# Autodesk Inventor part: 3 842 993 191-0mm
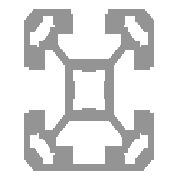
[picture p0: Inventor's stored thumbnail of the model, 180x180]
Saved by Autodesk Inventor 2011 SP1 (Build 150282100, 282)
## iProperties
Category: End -/-
Created: 2011-02
Part Number: 3 842 993 191-0mm
Document SubType Name: Modeling
Designer: SRW
Density: 2.71 g/cm^3
Categories: <MemberInstance><Categories><Category DisplayName="Structural Shapes" InternalName="089c4875-fa83-4c05-b084-43b9cc11f5ed" Mnemonic="GRDR"><CategoryParameter Dis
Stock Number: 3 842 993 191
Description: PROFILE 40x40 3S, -/-
Material: Aluminum-6061
Mass: 39.2557 g
Surface Area: 143.631 cm^2
Volume: 14.4855 cm^3
G_L: 25.000 mm
Author: SRW
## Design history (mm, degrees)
node "Blocks"
  sketch "40X403S"
    geometry: L1 (36.269, 30.157)-(33.329, 30.157); L2 (36.069, 38.957)-(36.069, 43.457); L3 (41.319, 38.957)-(36.069, 38.957); L4 (37.155, 32.457)-(41.319, 36.622); L5 (41.319, 36.622)-(41.319, 38.957); L6 (42.819, 40.457)-(42.819, 39.457); L7 (46.569, 36.707)-(46.569, 34.457); L8 (45.569, 36.707)-(46.569, 36.707); L9 (49.569, 34.457)-(49.569, 39.457); L10 (40.569, 40.457)-(42.819, 40.457); L11 (36.069, 43.457)-(26.069, 43.457); L12 (26.069, 43.457)-(26.069, 38.957); L13 (26.069, 38.957)-(20.819, 38.957); L14 (19.319, 40.457)-(21.569, 40.457); L15 (19.319, 39.457)-(19.319, 40.457); L16 (16.569, 43.457)-(16.569, 42.207); L17 (21.569, 43.457)-(16.569, 43.457); L18 (20.819, 38.957)-(20.819, 36.622); L19 (13.819, 39.457)-(12.569, 39.457); L20 (17.069, 35.007)-(19.605, 35.007); L21 (15.569, 34.457)-(15.569, 36.707); L22 (12.569, 39.457)-(12.569, 34.457); L23 (24.983, 32.457)-(37.155, 32.457); L24 (20.819, 36.622)-(24.983, 32.457); L25 (19.605, 35.007)-(23.569, 31.043); L26 (11.069, 30.757)-(12.569, 30.757); L27 (28.808, 30.157)-(25.869, 30.157); L28 (29.076, 29.543)-(28.808, 30.157); L29 (17.069, 29.957)-(17.069, 35.007); L30 (12.569, 29.957)-(17.069, 29.957); L31 (12.569, 30.757)-(12.569, 29.957); L32 (11.069, 41.957)-(11.069, 30.757); L33 (48.069, 44.957)-(14.069, 44.957); L34 (15.569, 36.707)-(16.569, 36.707); L35 (49.569, 19.157)-(49.569, 19.957); L36 (51.069, 19.157)-(49.569, 19.157); L37 (49.569, 10.457)-(49.569, 15.457); L38 (48.319, 10.457)-(49.569, 10.457); L39 (46.569, 15.457)-(46.569, 13.207); L40 (46.569, 13.207)-(45.569, 13.207); L41 (45.069, 19.957)-(45.069, 14.907); L42 (49.569, 19.957)-(45.069, 19.957); L43 (51.069, 7.957)-(51.069, 19.157); L44 (42.533, 14.907)-(38.569, 18.872); L45 (37.155, 17.457)-(41.119, 13.493); L46 (45.069, 14.907)-(42.533, 14.907); L47 (41.119, 13.493)-(41.119, 10.957); L48 (41.119, 10.957)-(36.069, 10.957); L49 (36.069, 6.457)-(36.869, 6.457); L50 (36.069, 10.957)-(36.069, 6.457); L51 (42.819, 9.457)-(40.569, 9.457); L52 (36.869, 6.457)-(36.869, 4.957); L53 (45.569, 6.457)-(45.569, 7.707); L54 (40.569, 6.457)-(45.569, 6.457); L55 (36.869, 4.957)-(48.069, 4.957); L56 (42.819, 10.457)-(42.819, 9.457); L57 (23.569, 31.043)-(23.569, 18.872); L58 (33.329, 19.757)-(36.269, 19.757); L59 (36.269, 19.757)-(36.269, 22.697); L60 (33.062, 20.372)-(33.329, 19.757); L61 (36.269, 22.697)-(35.654, 22.964); L62 (28.808, 19.757)-(29.076, 20.372); L63 (24.983, 17.457)-(37.155, 17.457); L64 (35.654, 26.951)-(36.269, 27.218)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; A1 r 2.75 centre (45.569, 39.457) between (42.819, 39.457) and (45.569, 36.707); A2 r 1.5 centre (48.069, 34.457) between (46.569, 34.457) and (49.569, 34.457); A3 r 1.5 centre (21.569, 41.957) between (21.569, 40.457) and (21.569, 43.457); A4 r 2.75 centre (16.569, 39.457) between (16.569, 36.707) and (19.319, 39.457); A5 r 2.75 centre (16.569, 39.457) between (16.569, 42.207) and (13.819, 39.457); A6 r 3 centre (14.069, 41.957) between (14.069, 44.957) and (11.069, 41.957); A7 r 1.5 centre (14.069, 34.457) between (12.569, 34.457) and (15.569, 34.457); A8 r 3 centre (48.069, 7.957) between (48.069, 4.957) and (51.069, 7.957); A9 r 1.5 centre (48.069, 15.457) between (49.569, 15.457) and (46.569, 15.457); A10 r 2.75 centre (45.569, 10.457) between (45.569, 7.707) and (48.319, 10.457); A11 r 2.75 centre (45.569, 10.457) between (45.569, 13.207) and (42.819, 10.457); A12 r 1.5 centre (40.569, 7.957) between (40.569, 9.457) and (40.569, 6.457); A13 r 5 centre (31.069, 24.957) between (29.076, 20.372) and (33.062, 20.372); A14 r 5 centre (31.069, 24.957) between (35.654, 22.964) and (35.654, 26.951); A15 r 5 centre (31.069, 24.957) between (33.062, 29.543) and (29.076, 29.543); A16 r 5 centre (31.069, 24.957) between (26.483, 26.951) and (26.483, 22.964); A17 r 3 centre (14.069, 7.957) between (11.069, 7.957) and (14.069, 4.957); A18 r 2.75 centre (16.569, 10.457) between (19.319, 10.457) and (16.569, 13.207); A19 r 1.5 centre (14.069, 15.457) between (15.569, 15.457) and (12.569, 15.457); A20 r 2.75 centre (16.569, 10.457) between (13.819, 10.457) and (16.569, 7.707); A21 r 1.5 centre (21.569, 7.957) between (21.569, 6.457) and (21.569, 9.457); A22 r 3 centre (48.069, 41.957) between (51.069, 41.957) and (48.069, 44.957); A23 r 1.5 centre (40.569, 41.957) between (40.569, 43.457) and (40.569, 40.457); A24 r 2.75 centre (45.569, 39.457) between (48.319, 39.457) and (45.569, 42.207); 1 further point
    constraints: 208 end point, 48 point on circle, 24 centre point, 1 coincident
node "Start Plane"
node "End Plane"
sketch "Sketch1"
  geometry: 1 further point
  constraints: 1 other
extrude "Body" new body sketch "Sketch1" stored distance "d4" = 0.13; taper "d5" = 0 deg
node "Driven Length"
  sketch "Sketch51"
    geometry: L1 (0, 0)-(10, 0) reference
    constraints: 2 end point, 1 horizontal
  workplane "Work Plane22"
  sketch "Sketch52"
    geometry: L1 (-28, 0)-(28, 0) reference; L2 (-28, 25)-(28, 25) reference
    dimensions: "d7" = 25 distance between parallel lines of L1 L2 (derived)
sketch "Sketch9"
  geometry: 1 further point
hole "M12/-" sketch "Sketch9" at (0, 0) diameter "d17" = 10.106; stored, may be unused: countersink angle "d21" = 90 deg, drill point angle "d23" = 118 deg; dims "d18" = 6, "d19" = 4, "d20" = 2, "d22" = 55
sketch "Sketch10"
  geometry: 1 further point
hole "-/M12" sketch "Sketch10" at (0, 0) diameter "d24" = 10.106; stored, may be unused: countersink angle "d28" = 90 deg, drill point angle "d30" = 118 deg; dims "d25" = 6, "d26" = 4, "d27" = 2, "d29" = 55
sketch "Sketch11"
  geometry: L1 (-13.7, 0)-(12.2, 0) reference; C1 r 8.5 at (0, 20); 1 further point
  constraints: 1 centre point, 1 vertical alignment
  dimensions: "d31" = 20 distance from line of C1.centre L1; "d32" = 17 diameter of C1
extrude "D17/-" cut sketch "Sketch11" stored distance "d33" = 10; taper "d34" = 0 deg
sketch "Sketch12"
  geometry: L1 (-13.7, 25)-(12.2, 25) reference; C1 r 8.5 at (0, 5); 1 further point
  constraints: 1 centre point, 1 vertical alignment
  dimensions: "d35" = 17 diameter of C1; "d36" = 20 distance from line of L1 C1.centre
extrude "-/D17" cut sketch "Sketch12" stored distance "d37" = 10; taper "d38" = 0 deg
sketch "Sketch13"
  geometry: L1 (-12.98, 0)-(7.88, 0) reference; C1 r 4.9 at (0, 20); 1 further point
  constraints: 1 centre point, 1 vertical alignment
  dimensions: "d39" = 9.8 diameter of C1; "d40" = 20 distance from line of C1.centre L1
extrude "D9.8/-" cut sketch "Sketch13" stored distance "d41" = 10; taper "d42" = 0 deg
sketch "Sketch14"
  geometry: L1 (-12.98, 25)-(7.88, 25) reference; C1 r 4.9 at (0, 5); 1 further point
  constraints: 1 centre point, 1 vertical alignment
  dimensions: "d43" = 9.8 diameter of C1; "d44" = 20 distance from line of L1 C1.centre
extrude "-/D9.8" cut sketch "Sketch14" stored distance "d45" = 10; taper "d46" = 0 deg
sketch "Sketch15"
  geometry: L1 (-6.86, 25)-(6.86, 25) reference; C1 r 4.9 at (0, 5); 1 further point
  constraints: 1 centre point, 1 vertical alignment
  dimensions: "d47" = 9.8 diameter of C1; "d48" = 20 distance from line of L1 C1.centre
extrude "-/D9.8VS" cut sketch "Sketch15" stored distance "d49" = 10; taper "d50" = 0 deg
sketch "Sketch26"
  geometry: L1 (-6.86, 0)-(6.86, 0) reference; C1 r 4.9 at (0, 20); 1 further point
  constraints: 1 centre point, 1 vertical alignment
  dimensions: "d62" = 9.8 diameter of C1; "d65" = 20 distance from line of L1 C1.centre
extrude "D9.8VS/-" cut sketch "Sketch26" stored distance "d63" = 10; taper "d64" = 0 deg
sketch "Sketch37"
  geometry: L1 (-11.9, 0)-(11.9, 0) reference; L2 (-11.9, 25)-(11.9, 25) reference; C1 r 8.5 at (0, 20); 1 further point
  constraints: 1 centre point, 1 vertical alignment
  dimensions: "d76" = 20 distance from line of C1.centre L1; "d77" = 17 diameter of C1
extrude "D17VS/-" cut sketch "Sketch37" stored distance "d78" = 10; taper "d79" = 0 deg
sketch "Sketch38"
  geometry: L1 (-11.9, 25)-(11.9, 25) reference; C1 r 8.5 at (0, 5); 1 further point
  constraints: 1 centre point, 1 vertical alignment
  dimensions: "d80" = 17 diameter of C1; "d81" = 20 distance from line of L1 C1.centre
extrude "-/D17VS" cut sketch "Sketch38" stored distance "d82" = 10; taper "d83" = 0 deg
body "Solid1"
node "40X403S:1"
other parameters: "Length" = 25, "G_OFFSET_START" = 0 [user parameter; used in 2 equation terms], "G_OFFSET_END" = 0 [user parameter; used in 2 equation terms], "d2" = 0 (computed from G_OFFSET_START), "d3" = 25 (= Length + G_OFFSET_END), "G_L" = 25 (= d7) [user parameter], "Length2" = 25 (= G_OFFSET_START + Length + G_OFFSET_END) [user parameter], "d96" = 90 deg
